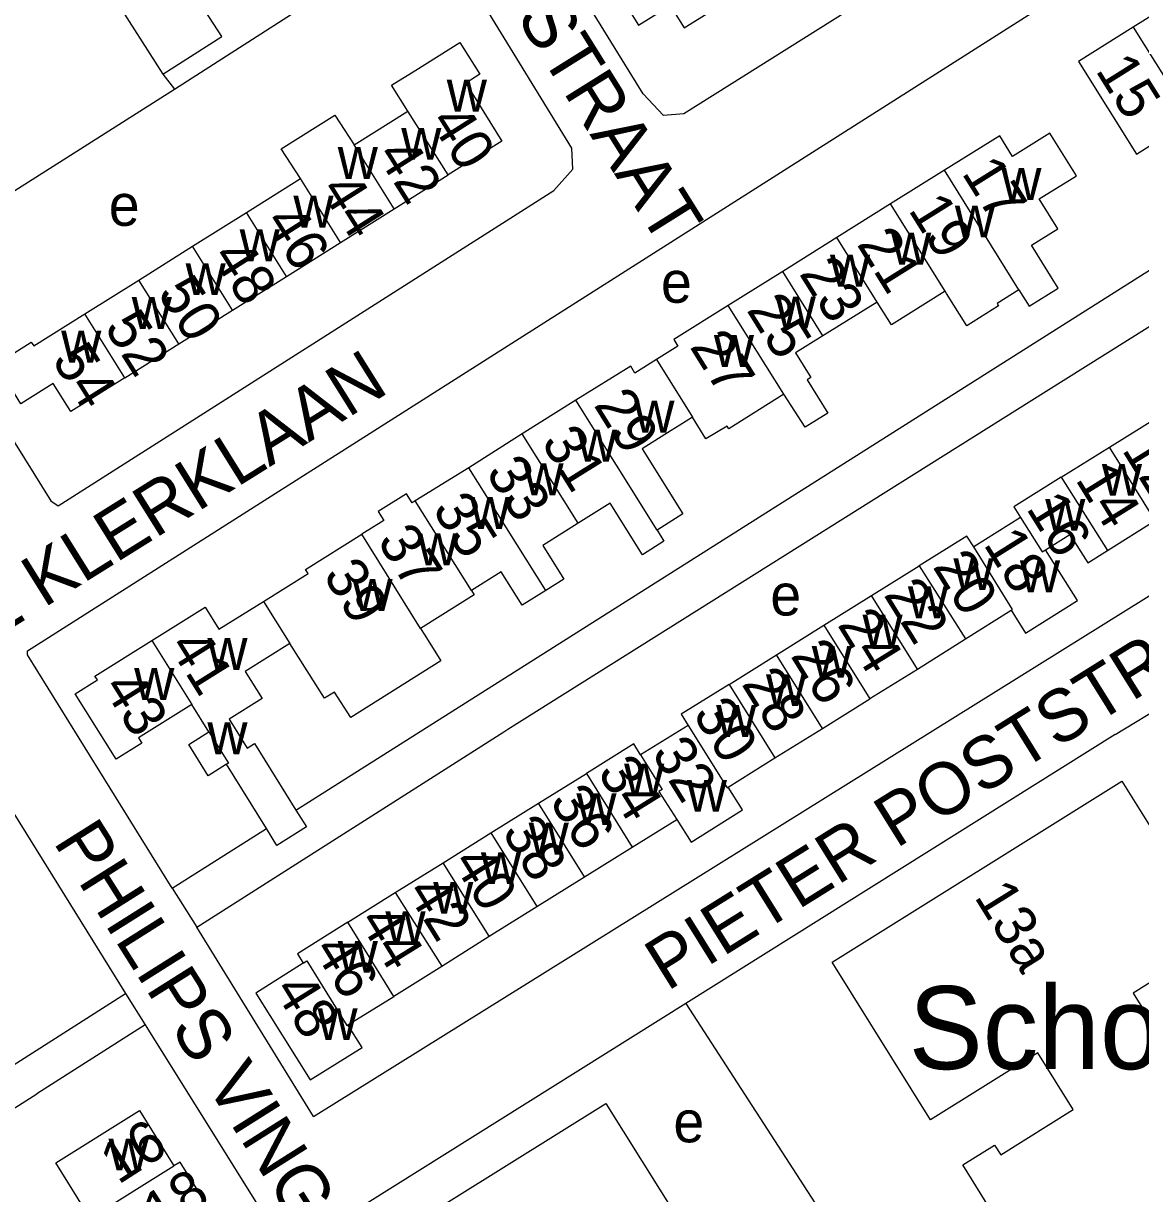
# Model space of a CAD drawing. Extents: x 158848 to 160613, y 385889 to 387762.
# Drawn here: x 159734 to 159841.7, y 386022.4 to 386135.1 of the extents above; entities that cross this region are included whole.
import ezdxf

# ---------------------------------------------------------------- set-up
doc = ezdxf.new("R2010")
doc.units = 0
for name, color, linetype in [('BLT_Basislijn', 7, 'Continuous'), ('BLT_Bebouwing', 7, 'Continuous'), ('BLT_Bebouwing_beschrifting', 7, 'Continuous'), ('BLT_Centroide', 7, 'Continuous'), ('BLT_Huisnummer', 7, 'Continuous'), ('BLT_Huisnummer_ tussenligend', 7, 'Continuous'), ('BLT_Onderverdeling_panden', 7, 'Continuous'), ('BLT_Straatnaam', 7, 'Continuous')]:
    doc.layers.add(name, color=color, linetype=linetype)

msp = doc.modelspace()

# ---------------------------------------------------------------- linework, layer by layer
at = {"layer": 'BLT_Basislijn'}
for p, q in [((159748.59, 386128.77), (159773.6, 386144.78)), ((159747.48, 386130.21), (159748.59, 386128.77)), ((159722.33, 386112.11), (159748.59, 386128.77)), ((159832.6, 386099.65), (159864.36, 386119.63)), ((159760.3, 386059.31), (159851.79, 386117.16)), ((159762, 386029.78), (159876.02, 386100.84)), ((159839.24, 386066.59), (159849.59, 386072.9)), ((159750.74, 386048.04), (159780.34, 386066.85)), ((159839.24, 386066.59), (159797.87, 386040.67)), ((159748.37, 386051.77), (159757.46, 386057.52)), ((159748.37, 386051.77), (159750.74, 386048.04)), ((159762, 386029.78), (159750.74, 386048.04)), ((159692.12, 386008.65), (159743.88, 386041.65)), ((159743.88, 386041.65), (159745.78, 386038.63)), ((159797.87, 386040.67), (159767.16, 386021.44)), ((159797.87, 386040.67), (159812.39, 386018.27)), ((159745.78, 386038.63), (159735.35, 386031.97)), ((159718.75, 386021.55), (159735.35, 386031.97))]:
    msp.add_line(p, q, dxfattribs=at)
for points in [[(159834.08, 386182.64), (159844.13, 386166.67), (159848.84, 386159.17), (159848.48, 386158.57), (159843.69, 386155.27), (159797.68, 386126.37), (159795.72, 386126.21), (159793.75, 386128.31), (159781.05, 386148.93)], [(159748.37, 386051.77), (159734.43, 386074.27), (159734.43, 386074.65), (159846.2, 386145.66), (159847.14, 386145.64), (159848.36, 386145.17), (159861.9, 386123.55)], [(159722.33, 386112.11), (159736.69, 386089.11), (159737.39, 386088.62), (159785.14, 386119), (159786.99, 386121.06), (159786.89, 386123.07), (159773.6, 386144.78)], [(159780.34, 386066.85), (159780.71, 386067.1), (159832.6, 386099.65)], [(159692.12, 386008.65), (159676.27, 386034.2), (159676.18, 386037.04), (159677.03, 386038.35), (159677.99, 386039.14), (159709.56, 386058.79), (159724.76, 386067.89), (159726.82, 386067.93), (159729.37, 386064.99), (159743.88, 386041.65)], [(159745.78, 386038.63), (159746.11, 386038.12), (159762.83, 386011.31)]]:
    msp.add_lwpolyline(points, dxfattribs=at)
at = {"layer": 'BLT_Bebouwing'}
for p, q in [((159742.57, 386137.91), (159747.48, 386130.21)), ((159765.92, 386123.4), (159771.09, 386126.64)), ((159755.53, 386116.88), (159760.73, 386120.14)), ((159769.78, 386117.24), (159774.98, 386120.5)), ((159822.81, 386120.95), (159817.61, 386117.7)), ((159750.34, 386113.62), (159755.53, 386116.88)), ((159764.59, 386113.98), (159769.78, 386117.24)), ((159817.61, 386117.7), (159812.44, 386114.47)), ((159812.44, 386114.47), (159807.21, 386111.2)), ((159745.15, 386110.36), (159750.34, 386113.62)), ((159759.4, 386110.72), (159764.59, 386113.98)), ((159807.21, 386111.2), (159801.97, 386107.93)), ((159739.95, 386107.11), (159745.15, 386110.36)), ((159754.2, 386107.46), (159759.4, 386110.72)), ((159816.31, 386108.25), (159811.08, 386104.99)), ((159749.01, 386104.21), (159754.2, 386107.46)), ((159743.82, 386100.95), (159749.01, 386104.21)), ((159797.11, 386104.01), (159795.04, 386102.71)), ((159795.04, 386102.71), (159792.97, 386101.41)), ((159787.27, 386098.78), (159782.11, 386095.55)), ((159838.69, 386094.27), (159843.29, 386097.14)), ((159782.11, 386095.55), (159776.98, 386092.29)), ((159834.05, 386091.38), (159838.69, 386094.27)), ((159776.98, 386092.29), (159771.8, 386089.1)), ((159830.14, 386087.48), (159825.62, 386084.66)), ((159815.78, 386079.98), (159820.37, 386082.85)), ((159777.47, 386080.05), (159772.32, 386076.8)), ((159811.19, 386077.12), (159815.78, 386079.98)), ((159824.84, 386075.8), (159829.24, 386078.55)), ((159806.62, 386074.27), (159811.19, 386077.12)), ((159802.04, 386071.42), (159806.62, 386074.27)), ((159815.62, 386070.04), (159820.19, 386072.89)), ((159798.09, 386067.46), (159793.52, 386064.62)), ((159806.46, 386064.33), (159811.04, 386067.18)), ((159757.46, 386057.52), (159753.6, 386063.72)), ((159783.69, 386059.97), (159788.29, 386062.84)), ((159779.1, 386057.11), (159783.69, 386059.97)), ((159792.71, 386055.72), (159797, 386058.39)), ((159774.5, 386054.24), (159779.1, 386057.11)), ((159788.12, 386052.87), (159792.71, 386055.72)), ((159769.88, 386051.36), (159774.5, 386054.24)), ((159765.32, 386048.5), (159769.88, 386051.36)), ((159778.93, 386047.15), (159783.53, 386050.01)), ((159769.74, 386041.37), (159774.36, 386044.27))]:
    msp.add_line(p, q, dxfattribs=at)
for points in [[(159799.06, 386144.09), (159797.45, 386146.58), (159795.13, 386145.13), (159790.9, 386142.48), (159791.88, 386140.9), (159790.22, 386139.86), (159793.32, 386134.91), (159796.36, 386136.82), (159797.7, 386134.68), (159802.91, 386137.95)], [(159747.48, 386130.21), (159753.15, 386133.83), (159750.8, 386137.51), (159748.7, 386136.2), (159746.17, 386140.17)], [(159844.83, 386128.58), (159850.1, 386131.89), (159846.26, 386138.03), (159840.98, 386134.72)], [(159840.98, 386134.72), (159835.7, 386131.42), (159841.29, 386122.49), (159844.46, 386124.48), (159846.9, 386120.57), (159848.9, 386121.83)], [(159771.09, 386126.64), (159769.52, 386129.13), (159771.85, 386130.59), (159776.09, 386133.25), (159778.01, 386130.19), (159776.66, 386129.34), (159780.16, 386123.76), (159774.98, 386120.5)], [(159760.73, 386120.14), (159758.88, 386123.01), (159764.04, 386126.25), (159765.92, 386123.4)], [(159829.97, 386109.43), (159830.95, 386107.85), (159833.75, 386109.6), (159831.18, 386113.72), (159833.73, 386115.31), (159831.93, 386118.18), (159835.52, 386120.42), (159832.95, 386124.52), (159829.37, 386122.28), (159828.13, 386124.27), (159822.81, 386120.95)], [(159822.87, 386109.29), (159817.68, 386106.04), (159816.31, 386108.25)], [(159829.97, 386109.43), (159827.87, 386108.12), (159828.02, 386107.87), (159824.96, 386105.95), (159823.01, 386109.07), (159822.87, 386109.29)], [(159801.97, 386107.93), (159796.71, 386104.65), (159797.11, 386104.01)], [(159743.82, 386100.95), (159738.62, 386097.69), (159736.92, 386100.41), (159733.8, 386098.45), (159731.42, 386102.25), (159734.8, 386104.39), (159735.03, 386104.02), (159739.95, 386107.11)], [(159811.08, 386104.99), (159808.45, 386103.35), (159809.93, 386100.99), (159809.56, 386100.76), (159811.57, 386097.55), (159809.39, 386096.19), (159807.32, 386099.36)], [(159792.97, 386101.41), (159792.56, 386102.06), (159787.27, 386098.78)], [(159807.32, 386099.36), (159802.01, 386096.05)], [(159798.53, 386097.17), (159797.3, 386096.4), (159796.46, 386095.87)], [(159802.01, 386096.05), (159801.86, 386096.3), (159799.79, 386095.07), (159798.53, 386097.17)], [(159796.46, 386095.87), (159793.68, 386094.11), (159797.6, 386087.85), (159795.1, 386086.27)], [(159834.05, 386091.38), (159829.47, 386088.52), (159830.14, 386087.48)], [(159771.8, 386089.1), (159771.5, 386088.92), (159770.96, 386089.77), (159768.22, 386088.06), (159768.76, 386087.2), (159766.64, 386085.88)], [(159795.1, 386086.27), (159795.77, 386085.2), (159793.7, 386083.91), (159790.58, 386088.88), (159787.5, 386086.94)], [(159787.5, 386086.94), (159784.09, 386084.79), (159786.11, 386081.56), (159784.38, 386080.47)], [(159838.51, 386084.32), (159843.09, 386087.2)], [(159757.19, 386079.41), (159761.49, 386082.09), (159761.23, 386082.49), (159766.64, 386085.88)], [(159825.62, 386084.66), (159824.96, 386085.71), (159820.37, 386082.85)], [(159832.53, 386084.38), (159834.88, 386085.86), (159836.6, 386083.11)], [(159829.24, 386078.55), (159830.6, 386076.36), (159835.62, 386079.49), (159832.53, 386084.38)], [(159836.6, 386083.11), (159838.51, 386084.32)], [(159784.38, 386080.47), (159782.11, 386079.05), (159780.09, 386082.27), (159777.21, 386080.45)], [(159777.21, 386080.45), (159777.47, 386080.05)], [(159746.43, 386075.64), (159751.56, 386078.84), (159752.88, 386076.72), (159757.19, 386079.41)], [(159772.32, 386076.8), (159772.72, 386076.17), (159774.28, 386073.7), (159765.58, 386068.21), (159764.02, 386070.68), (159763.07, 386070.08), (159759.73, 386075.37)], [(159750.27, 386069.48), (159745.12, 386066.27), (159745.44, 386065.76), (159742.97, 386064.22), (159739.04, 386070.51), (159741.17, 386071.84), (159740.94, 386072.2), (159746.43, 386075.64)], [(159759.73, 386075.37), (159755.4, 386072.67), (159757.05, 386070.04), (159753.88, 386068.06), (159755.61, 386065.28), (159756.3, 386065.71), (159760.3, 386059.31)], [(159820.19, 386072.89), (159824.84, 386075.8)], [(159802.04, 386071.42), (159797.42, 386068.54), (159798.09, 386067.46)], [(159751.92, 386066.84), (159750.27, 386069.48)], [(159811.04, 386067.18), (159815.62, 386070.03)], [(159753.6, 386063.72), (159751.85, 386062.62), (159749.98, 386065.63), (159751.92, 386066.84)], [(159793.52, 386064.62), (159792.86, 386065.69), (159788.29, 386062.84)], [(159801.97, 386061.5), (159806.46, 386064.33)], [(159797, 386058.39), (159798.38, 386056.2), (159803.34, 386059.32), (159801.97, 386061.5)], [(159760.3, 386059.31), (159761.32, 386057.68), (159758.47, 386055.9), (159757.46, 386057.52)], [(159783.53, 386050.01), (159788.12, 386052.87)], [(159765.32, 386048.5), (159760.45, 386045.45), (159761.01, 386044.56)], [(159774.36, 386044.27), (159778.93, 386047.15)], [(159761.01, 386044.56), (159756.43, 386041.68), (159761.67, 386033.33), (159766.67, 386036.43), (159765.32, 386038.62)], [(159765.32, 386038.62), (159769.74, 386041.36)], [(159740.47, 386019.98), (159737.15, 386025.34), (159745.22, 386030.36), (159748.55, 386025.02)], [(159751.51, 386018.93), (159752.7, 386019.66), (159749.14, 386025.38), (159748.55, 386025.02)]]:
    msp.add_lwpolyline(points, dxfattribs=at)
for points in [[(159811.97, 386044.65), (159839.88, 386062.09), (159849.36, 386046.93), (159840.97, 386041.68), (159844.4, 386036.21), (159849.68, 386039.49), (159849.07, 386040.46), (159852.23, 386042.44), (159854.78, 386038.37), (159856.61, 386039.52), (159860.82, 386032.68), (159829.2, 386012.91), (159824.89, 386019.7), (159827.09, 386021.07), (159824.56, 386025.14), (159827.62, 386027.04), (159828.22, 386026.08), (159835.2, 386030.45), (159831.79, 386035.92), (159821.45, 386029.47)], [(159770.78, 386018.94), (159790.17, 386031.04), (159800.51, 386014.52), (159781.08, 386002.38)]]:
    msp.add_lwpolyline(points, close=True, dxfattribs=at)
at = {"layer": 'BLT_Onderverdeling_panden'}
for p, q in [((159840.98, 386134.72), (159844.83, 386128.58)), ((159774.98, 386120.5), (159771.09, 386126.64)), ((159769.78, 386117.24), (159765.92, 386123.4)), ((159764.59, 386113.98), (159760.73, 386120.14)), ((159829.97, 386109.43), (159822.81, 386120.95)), ((159759.4, 386110.72), (159755.53, 386116.88)), ((159822.87, 386109.29), (159817.61, 386117.7)), ((159816.31, 386108.25), (159812.44, 386114.47)), ((159754.2, 386107.46), (159750.34, 386113.62)), ((159811.08, 386104.99), (159807.21, 386111.2)), ((159749.01, 386104.21), (159745.15, 386110.36)), ((159807.32, 386099.36), (159801.97, 386107.93)), ((159743.82, 386100.95), (159739.95, 386107.11)), ((159795.04, 386102.71), (159798.53, 386097.17)), ((159795.1, 386086.27), (159787.27, 386098.78)), ((159787.5, 386086.94), (159782.11, 386095.55)), ((159843.09, 386087.2), (159838.69, 386094.27)), ((159784.38, 386080.47), (159776.98, 386092.29)), ((159834.05, 386091.38), (159838.51, 386084.32)), ((159777.21, 386080.45), (159771.8, 386089.1)), ((159772.32, 386076.8), (159766.64, 386085.88)), ((159820.37, 386082.85), (159824.84, 386075.8)), ((159820.19, 386072.89), (159815.78, 386079.98)), ((159757.19, 386079.41), (159759.73, 386075.37)), ((159811.19, 386077.12), (159815.62, 386070.03)), ((159746.43, 386075.64), (159750.27, 386069.48)), ((159811.04, 386067.18), (159806.62, 386074.27)), ((159802.04, 386071.42), (159806.46, 386064.33)), ((159788.29, 386062.84), (159792.71, 386055.72)), ((159788.12, 386052.87), (159783.69, 386059.97)), ((159779.1, 386057.11), (159783.53, 386050.01)), ((159778.93, 386047.15), (159774.5, 386054.24)), ((159769.88, 386051.36), (159774.36, 386044.27)), ((159769.74, 386041.36), (159765.32, 386048.5)), ((159740.47, 386019.98), (159748.55, 386025.02))]:
    msp.add_line(p, q, dxfattribs=at)
for points in [[(159830.14, 386087.48), (159832.21, 386084.18), (159832.53, 386084.38)], [(159829.24, 386078.55), (159829.36, 386078.62), (159825.62, 386084.66)], [(159798.09, 386067.46), (159801.87, 386061.44), (159801.97, 386061.5)], [(159751.92, 386066.84), (159753.79, 386063.84), (159753.6, 386063.72)], [(159793.52, 386064.62), (159795.59, 386061.3), (159795.28, 386061.11), (159797, 386058.39)], [(159761.01, 386044.56), (159761.35, 386044.77), (159765.21, 386038.55), (159765.32, 386038.62)]]:
    msp.add_lwpolyline(points, dxfattribs=at)

# ---------------------------------------------------------------- texts
at = {"layer": 'BLT_Bebouwing_beschrifting'}
msp.add_text('School', height=8, dxfattribs=at).set_placement((159819.35, 386034.35))
at = {"layer": 'BLT_Centroide'}
for s, p in [('w', (159774.84, 386126.59)), ('w', (159770.45, 386121.95)), ('w', (159764.33, 386120.11)), ('w', (159828.28, 386118.09)), ('e', (159742.27, 386115.59)), ('w', (159760.06, 386115.42)), ('w', (159823.8, 386114.47)), ('w', (159754.88, 386112.17)), ('w', (159817.66, 386111.86)), ('w', (159811.77, 386109.73)), ('w', (159749.67, 386108.92)), ('e', (159795.48, 386108.18)), ('w', (159744.48, 386105.66)), ('w', (159806.53, 386105.7)), ('w', (159737.68, 386102.41)), ('w', (159800.58, 386102)), ('w', (159792.91, 386095.66)), ('w', (159787.38, 386092.88)), ('w', (159782.23, 386089.64)), ('w', (159837.97, 386089.58)), ('w', (159777.08, 386086.39)), ('w', (159832.51, 386086.21)), ('w', (159772.03, 386082.89)), ('w', (159823.66, 386080.5)), ('w', (159830.07, 386080.28)), ('w', (159765.75, 386078.5)), ('e', (159806.02, 386078.05)), ('w', (159819.28, 386077.78)), ('w', (159814.9, 386075.07)), ('w', (159751.77, 386072.81)), ('w', (159810.01, 386072.05)), ('w', (159744.72, 386069.91)), ('w', (159805.6, 386069.32)), ('w', (159800.8, 386066.35)), ('w', (159751.77, 386064.69)), ('w', (159791.93, 386060.71)), ('w', (159797.97, 386059.14)), ('w', (159787.33, 386057.86)), ('w', (159782.73, 386055.02)), ('w', (159778.13, 386052.17)), ('w', (159773.53, 386049.32)), ('w', (159768.93, 386046.47)), ('w', (159764.33, 386043.63)), ('w', (159762.38, 386037.15)), ('e', (159796.68, 386027.3)), ('w', (159742.24, 386024.59))]:
    msp.add_text(s, height=4, dxfattribs=at).set_placement(p)
at = {"layer": 'BLT_Huisnummer'}
for s, rotation, p in [('15', 302.0567, (159837.29, 386130.58)), ('40', 302.3654, (159773.14, 386125.64)), ('17', 301.9366, (159824.4, 386120.69)), ('44', 302.3654, (159762.58, 386119.07)), ('21', 301.9366, (159814.29, 386113.84)), ('48', 302.3654, (159752.12, 386112.65)), ('27', 301.9366, (159798.19, 386103.96)), ('54', 302.1031, (159736.72, 386102.67)), ('29', 301.9366, (159788.94, 386098.34)), ('33', 301.9366, (159778.53, 386091.84)), ('14', 301.845, (159835.35, 386091.17)), ('18', 302.0052, (159826.5, 386084.93)), ('39', 301.9366, (159762.85, 386081.94)), ('22', 301.845, (159816.88, 386080.06)), ('41', 301.9444, (159747.98, 386075.11)), ('26', 301.845, (159807.91, 386074.18)), ('43', 301.9465, (159741.63, 386071.13)), ('30', 301.845, (159798.48, 386068.56)), ('34', 301.845, (159789.29, 386062.96)), ('38', 301.845, (159780.08, 386057.18)), ('42', 301.845, (159770.89, 386051.43)), ('13a', 301.8596, (159825.61, 386050.96)), ('48', 301.845, (159758.1, 386042.01)), ('16', 32.8463, (159743.18, 386023.17))]:
    msp.add_text(s, height=4, rotation=rotation, dxfattribs=at).set_placement(p)
at = {"layer": 'BLT_Huisnummer_ tussenligend'}
for s, rotation, p in [('42', 302.3654, (159768, 386122.41)), ('19', 301.9366, (159819.26, 386117.14)), ('46', 302.3654, (159757.2, 386116.01)), ('23', 301.9366, (159808.74, 386111)), ('50', 302.3654, (159746.89, 386109.12)), ('25', 301.9366, (159803.67, 386107.49)), ('52', 302.3654, (159741.76, 386105.81)), ('31', 301.9366, (159783.87, 386094.74)), ('12', 301.755, (159839.84, 386094.02)), ('35', 301.9366, (159773.38, 386088.3)), ('16', 302.0052, (159830.61, 386088.39)), ('37', 301.9366, (159768.07, 386085.25)), ('20', 301.845, (159821.6, 386082.77)), ('24', 301.755, (159812.42, 386077.17)), ('28', 301.755, (159803.18, 386071.48)), ('32', 301.845, (159794.51, 386064.8)), ('36', 301.755, (159784.68, 386060.17)), ('40', 301.845, (159775.31, 386054.29)), ('44', 301.755, (159766.27, 386048.63)), ('46', 301.755, (159761.91, 386045.87)), ('18', 32.8463, (159747.24, 386018.38))]:
    msp.add_text(s, height=4, rotation=rotation, dxfattribs=at).set_placement(p)
at = {"layer": 'BLT_Straatnaam'}
for s, rotation, p in [('ANTHONY VAN OPBERGENSTRAAT', 302.0451, (159734.75, 386210.39)), ('DE KLERKLAAN', 31.9938, (159726.55, 386072.84)), ('PIETER POSTSTRAAT', 31.9493, (159796.08, 386041.8)), ('PHILIPS VINGBOONSSTRAAT', 302.2239, (159736.85, 386056.25))]:
    msp.add_text(s, height=5, rotation=rotation, dxfattribs=at).set_placement(p)

doc.saveas('drawing.dxf')
